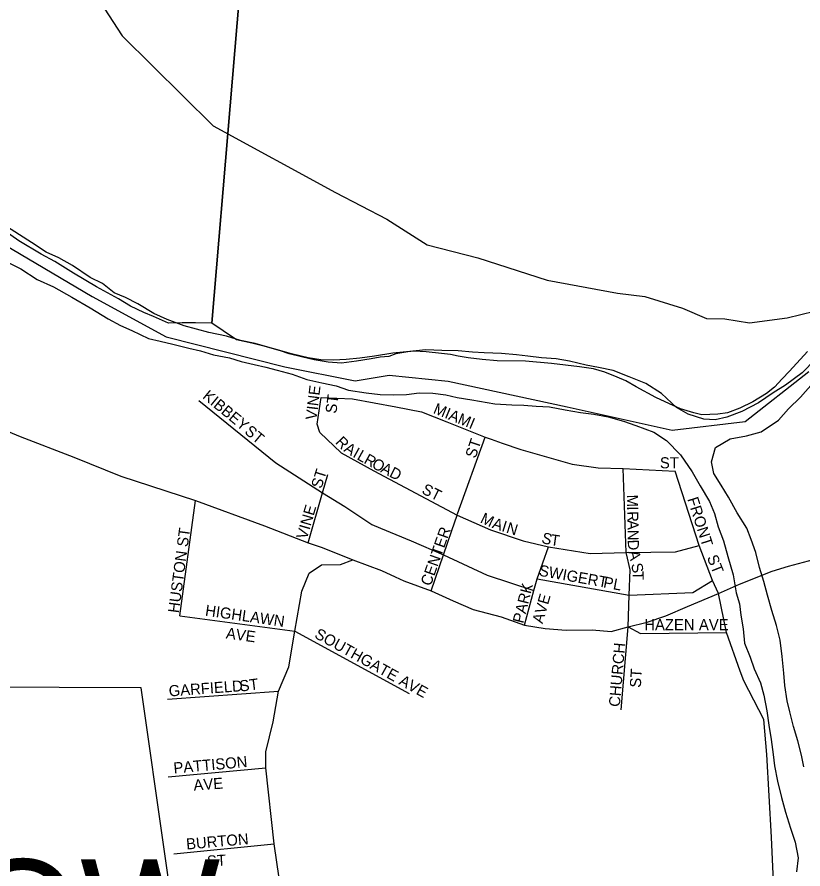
# Model space of a CAD drawing. Extents: x 1310247 to 1664935, y 284496 to 704931.
# Drawn here: x 1504369 to 1507915, y 496071 to 499915 of the extents above; entities that cross this region are included whole.
import ezdxf

# ---------------------------------------------------------------- set-up
doc = ezdxf.new("R2010")
doc.units = 0
for name, color, linetype in [('GM_P_State_Shield', 7, 'Continuous'), ('GM_X_City_Street', 7, 'Continuous'), ('GM_X_Corporation_Text', 7, 'Continuous'), ('GM_X_County', 7, 'Continuous'), ('GM_X_County_Road_Text', 7, 'Continuous'), ('GM_X_County_Subdivision', 7, 'Continuous'), ('GM_X_Interchange_Ramps', 7, 'Continuous'), ('GM_X_Major_Lake_Text', 7, 'Continuous'), ('GM_X_Rail_Line', 7, 'Continuous')]:
    doc.layers.add(name, color=color, linetype=linetype)

msp = doc.modelspace()

# ---------------------------------------------------------------- linework, layer by layer
at = {"layer": 'GM_P_State_Shield'}
for points in [[(1504152.3, 498118.9), (1504383.2, 498021.7), (1504625.4, 497929.6), (1504837.2, 497843.3), (1505174.2, 497733.5), (1505486.3, 497618.6), (1505682.3, 497542.5), (1505745.9, 497521.2), (1505884.5, 497466.3), (1506013, 497417.7), (1506075.5, 497389.1)], [(1506075.5, 497389.1), (1506114.1, 497371.5), (1506237.8, 497326.1), (1506336.3, 497281.6), (1506427.4, 497241.7), (1506553.5, 497208), (1506658.5, 497171.4), (1506752, 497155.5), (1506846.8, 497148.1), (1506964.2, 497149.3), (1507049.1, 497143.1), (1507126.4, 497163), (1507212.6, 497184.2), (1507296.2, 497212.9), (1507393.6, 497255.4), (1507533.4, 497314.1), (1507628.2, 497356.5), (1507775.5, 497415.2), (1507849.1, 497437.6), (1507962.7, 497467.6), (1508131.3, 497493.8), (1508329.7, 497516.3)]]:
    msp.add_lwpolyline(points, dxfattribs=at)
at = {"layer": 'GM_X_City_Street'}
for points in [[(1507971.6, 498370.8), (1507911.8, 498310.1), (1507836.1, 498253.9), (1507781, 498219.2), (1507713.6, 498174.8), (1507638.3, 498134.5), (1507571.4, 498110.1), (1507518.9, 498097.4), (1507466.8, 498100.7), (1507397.1, 498122.5), (1507343.7, 498153.9), (1507277, 498215.7), (1507205.9, 498261.6), (1507130.4, 498291.6), (1507058.9, 498319.4), (1506993, 498333.1), (1506937.1, 498344.5), (1506861.2, 498362.5), (1506801.3, 498372), (1506735.2, 498377.6), (1506673.1, 498385.2), (1506623.1, 498390.5), (1506555, 498396.2), (1506476.8, 498400.1), (1506424.7, 498403.5), (1506358.6, 498409.1), (1506286.4, 498410.9), (1506214.1, 498412.7), (1506125.6, 498404.9), (1506065.2, 498398.4), (1505982.6, 498384.4), (1505916.1, 498376.1), (1505853.7, 498369.6), (1505797.4, 498367), (1505739.3, 498368.5), (1505683.3, 498377.9), (1505607.5, 498395.8), (1505527.7, 498417.9), (1505444.1, 498442), (1505378.2, 498455.7), (1505314.4, 498475.3), (1505234.6, 498491.4), (1505178.7, 498506.8), (1505122.9, 498522.2), (1505047.4, 498550.2), (1504985.9, 498577.8), (1504914.7, 498621.6), (1504859.2, 498649.1), (1504807.6, 498670.4), (1504754.5, 498711.9), (1504699, 498739.3), (1504620.1, 498793.4), (1504558.7, 498829), (1504501.2, 498854.5), (1504434.1, 498898.3), (1504380.7, 498931.7), (1504321.5, 498969.3)], [(1504335.3, 498804.5), (1504386.8, 498779.2), (1504459.9, 498731.3), (1504533.3, 498697.3), (1504616.4, 498651.2), (1504699.5, 498603), (1504780.5, 498552.8), (1504835.9, 498523.4), (1504887.5, 498500), (1504962.9, 498464.1), (1505014.8, 498452.8), (1505072.6, 498439.3), (1505144.4, 498421.5), (1505196.3, 498408.1), (1505256, 498390.6), (1505328, 498376.8), (1505379.8, 498361.4), (1505439.6, 498347.9), (1505491.5, 498334.6), (1505543.3, 498321.3), (1505611.1, 498303.5), (1505676.8, 498279.8), (1505744.6, 498264.1), (1505808.5, 498250.5), (1505864.2, 498231), (1505944.2, 498219), (1506008.2, 498211.4), (1506066.4, 498210), (1506126.7, 498212.5), (1506183.1, 498219), (1506245.2, 498217.5), (1506303.3, 498210), (1506355.2, 498198.7), (1506421.1, 498187), (1506525.1, 498170.4), (1506601.2, 498164.5), (1506655.4, 498163.1), (1506711.5, 498159.7), (1506771.6, 498156.2), (1506841.5, 498142.4), (1506911.5, 498130.7), (1506971.5, 498123.1), (1507035.4, 498111.5), (1507105.2, 498091.7), (1507160.9, 498072.3), (1507242.4, 498042.2), (1507299.7, 498004.7), (1507362.2, 497939), (1507414.5, 497863.5), (1507451, 497800.4), (1507493.3, 497729.2), (1507516, 497674.5), (1507532.5, 497614), (1507557, 497551.2), (1507575.2, 497480.6), (1507599.2, 497397.8), (1507613.1, 497317.3), (1507627.9, 497266.8), (1507634.6, 497216.5), (1507645.1, 497154.1), (1507651.4, 497089.8), (1507675.9, 497027), (1507694.6, 496974.4), (1507723.1, 496911.6), (1507737.7, 496855.1), (1507752, 496784.6), (1507760.3, 496720.2), (1507770.7, 496655.8), (1507781, 496587.4), (1507785.7, 496537.1), (1507800, 496466.6), (1507818.2, 496394), (1507836.5, 496327.4), (1507858.7, 496254.6), (1507879.2, 496192), (1507893.4, 496121.5), (1507885.8, 496057.5)], [(1507918.1, 496531.8), (1507907.4, 496584.2), (1507891, 496648.8), (1507872.6, 496713.4), (1507856.2, 496779.9), (1507843.5, 496830.4), (1507833.2, 496898.8), (1507828.6, 496955), (1507820.5, 497029.4), (1507812.4, 497103.8), (1507796, 497170.3), (1507773.7, 497237.1), (1507755.4, 497305.7), (1507738.9, 497368.2), (1507718.5, 497430.9), (1507702.2, 497499.5), (1507681.6, 497558.1), (1507660.8, 497608.8), (1507618.4, 497678), (1507578.1, 497749.1), (1507545.4, 497802.1), (1507512.6, 497855), (1507501.9, 497907.4), (1507519.7, 497973.1), (1507586.9, 498011.5), (1507659.5, 498025.8), (1507726.3, 498044.1), (1507803.9, 498096.3), (1507849.4, 498147.3), (1507902.9, 498200.1), (1507960.8, 498264.8)]]:
    msp.add_lwpolyline(points, dxfattribs=at)
at = {"layer": 'GM_X_Corporation_Text'}
for points in [[(1505735.9, 498040.5), (1505723.4, 498078), (1505740.9, 498199)], [(1505740.9, 498199), (1505883.2, 498192.8), (1506077.9, 498156.6), (1506194, 498134.1), (1506308.9, 498089.2), (1506481.1, 498019.3), (1506507.8, 498009.7)], [(1505189.2, 498184.1), (1505537.4, 497903.2), (1505747.2, 497768.4), (1505848.3, 497707.2), (1505969.3, 497624.9), (1506009.2, 497608.4)], [(1505735.9, 498040.5), (1505832, 497948.2), (1505979.3, 497867), (1506354.4, 497667.5)], [(1506356.6, 497673.7), (1506481.1, 498019.3)], [(1506507.8, 498009.7), (1506557.3, 497991.9), (1506642.1, 497963.1), (1506874.3, 497897), (1506991.6, 497880.8), (1507104, 497878.3), (1507338.7, 497865.8)], [(1505682.3, 497542.5), (1505747.2, 497768.4), (1505772.1, 497850.8)], [(1507118.2, 497492.2), (1507116.8, 497498.3), (1507104, 497878.3)], [(1507533.4, 497314.1), (1507505.9, 497372.7), (1507446, 497530), (1507338.7, 497865.8)], [(1505103.9, 497212.9), (1505174.2, 497733.5)], [(1506237.8, 497326.1), (1506293.1, 497488.7), (1506330.4, 497598.5), (1506354.4, 497667.5), (1506356.6, 497673.7)], [(1506354.4, 497667.5), (1506504.8, 497601.1), (1506652.1, 497551.2), (1506767, 497523.8), (1506955.4, 497495), (1507116.8, 497498.3), (1507339.9, 497501.3), (1507446, 497530)], [(1506009.2, 497608.4), (1506147.8, 497551.2), (1506293.1, 497488.7), (1506489.8, 497396.4), (1506701, 497328.1)], [(1506658.5, 497171.4), (1506701, 497328.1), (1506715.3, 497380.7), (1506767, 497523.8)], [(1505624.3, 495659.1), (1505608.1, 495685.1), (1505574.8, 495855.8), (1505552, 496030), (1505529.1, 496185.1), (1505492.1, 496527), (1505491.8, 496600.2), (1505524.1, 496735.3), (1505549.3, 496873.5), (1505594.8, 496982.8), (1505622.6, 497144.1), (1505653.7, 497324.6), (1505687.2, 497405.2), (1505742.2, 497443.9), (1505828.3, 497445.1), (1505884.5, 497466.3)], [(1507126.4, 497163), (1507131.4, 497306.6), (1507135.2, 497420.2), (1507118.2, 497492.2)], [(1506715.3, 497380.7), (1507131.4, 497306.6), (1507417.3, 497319.1), (1507505.9, 497372.7)], [(1507631.8, 496964.1), (1507570.2, 497138), (1507533.4, 497314.1)], [(1505103.9, 497212.9), (1505622.6, 497144.1)], [(1507094.6, 496789.4), (1507126.4, 497163)], [(1507126.4, 497163), (1507181.4, 497133.1), (1507570.2, 497138)], [(1505622.6, 497144.1), (1506139, 496863)], [(1505048.6, 496836.9), (1505549.3, 496873.5)], [(1505051.2, 496486.5), (1505492.1, 496527)], [(1505076, 496138.7), (1505529.1, 496185.1)]]:
    msp.add_lwpolyline(points, dxfattribs=at)
at = {"layer": 'GM_X_County'}
for points in [[(1505662.2, 503437.3), (1505248.3, 498534.2), (1505174.4, 498535.5), (1505114.4, 498534.7), (1505052.4, 498533.8), (1504984.9, 498563.1), (1504941.3, 498581.9), (1504881.9, 498611), (1504826.5, 498644), (1504727.5, 498697.9), (1504624.7, 498759.8), (1504539.7, 498811.4), (1504478.3, 498844.5), (1504377.5, 498904.4), (1504288.7, 498966.1)], [(1507935.2, 498405.8), (1507853.6, 498317.3), (1507820.9, 498282), (1507786.2, 498244.6), (1507750.3, 498216.3), (1507689, 498178.5), (1507630.5, 498149.6), (1507574.1, 498128.6), (1507530.1, 498123.5), (1507458, 498120.8), (1507422.2, 498129.5), (1507362.5, 498146.6), (1507313, 498169.5), (1507251.5, 498198.6), (1507162.4, 498246.3), (1507115, 498273.2), (1507077.3, 498289.9), (1507021.7, 498312.9), (1506970, 498327.9), (1506906.2, 498337.1), (1506780.5, 498351.5), (1506662.8, 498361.7), (1506534.8, 498364.1), (1506466.9, 498369.3), (1506405.1, 498376.5), (1506359.3, 498385.3), (1506325.4, 498392), (1506283.5, 498396.8), (1506215.6, 498404), (1506159.7, 498407.1), (1506131.7, 498403.6), (1506077.5, 498394.6), (1506047.3, 498383.2), (1506007.3, 498379.9), (1505967.1, 498372.7), (1505900.9, 498361.9), (1505832.8, 498353.2), (1505772.9, 498358.3), (1505709.1, 498367.6), (1505659.3, 498380.5), (1505597.6, 498395.6), (1505557.9, 498408.4), (1505488.3, 498427.7), (1505428.5, 498442.8), (1505358.9, 498458.1), (1505299.7, 498499.2), (1505248.3, 498534.2), (1505662.2, 503437.3)]]:
    msp.add_lwpolyline(points, dxfattribs=at)
at = {"layer": 'GM_X_County_Road_Text'}
msp.add_lwpolyline([(1504762.6, 499954.6), (1504844.4, 499830.8), (1505253.7, 499424.5), (1505805.4, 499123.7), (1506037.7, 499003.2), (1506220, 498887.6), (1506447.4, 498828), (1506760.3, 498727), (1507078.3, 498669), (1507201.9, 498653.8), (1507371, 498600.8), (1507479.5, 498555.4), (1507562.8, 498552.9), (1507673.9, 498535.2), (1507842.9, 498558), (1507966.6, 498588.2), (1508208.8, 498777.5), (1508244.7, 498830.4)], dxfattribs=at)
at = {"layer": 'GM_X_County_Subdivision'}
msp.add_lwpolyline([(1507640.9, 495264.3), (1507686, 495328.7), (1507768.8, 495456.3), (1507801, 495569.4), (1507785.1, 495948.5), (1507773.5, 496214), (1507752.3, 496587.5), (1507737.5, 496746.1), (1507647.6, 496919.6), (1507631.8, 496964.1)], dxfattribs=at)
at = {"layer": 'GM_X_Major_Lake_Text'}
for points in [[(1504165.2, 498973.6), (1504708.1, 498654.6), (1505042.3, 498472.3), (1505577.5, 498335.9), (1505895.2, 498274.1), (1506047.7, 498298.4), (1506313.8, 498271.3), (1506851.3, 498156.9), (1507324.7, 498051.2), (1507653.7, 498089.6), (1507941, 498314.9)], [(1505142.2, 495390.9), (1504929.1, 496888.4), (1503819.6, 496892.3)]]:
    msp.add_lwpolyline(points, dxfattribs=at)

# ---------------------------------------------------------------- texts
at = {"layer": 'GM_X_Interchange_Ramps'}
msp.add_text('MORROW', height=500, rotation=0, dxfattribs=at).set_placement((1502091.8, 495614.1))
at = {"layer": 'GM_X_Rail_Line'}
for s, rotation, p in [('KIBBEY', 320.4772, (1505202.9, 498197.8)), ('VINE', 83.0927, (1505720.1, 498094.9)), ('ST', 82.8783, (1505809.8, 498123.9)), ('MIAMI', 337.4817, (1506243.4, 498128.9)), ('ST', 320.2016, (1505392.2, 498039.4)), ('R', 313.643, (1505802.7, 497994.1)), ('ST', 71.5607, (1506437.6, 497920.7)), ('A', 327.3031, (1505840.1, 497957.2)), ('I', 331.0012, (1505880.1, 497931.6)), ('L', 330.8313, (1505899.3, 497921)), ('R', 330.8275, (1505930.1, 497903.8)), ('O', 332.1155, (1505965.7, 497883.9)), ('ST', 0, (1507269.4, 497878.8)), ('A', 333.4048, (1506005.7, 497862.8)), ('D', 333.4347, (1506045.1, 497843.1)), ('ST', 72.6452, (1505742.4, 497784.2)), ('ST', 333.435, (1506191.2, 497767.8)), ('M', 271.0383, (1507120.4, 497759.5)), ('FRONT', 287.6491, (1507392.7, 497740.2)), ('VINE', 73.8118, (1505676.3, 497555.2)), ('I', 271.0593, (1507121.3, 497706.7)), ('M', 334.5022, (1506455.4, 497635.7)), ('A', 341.2367, (1506509, 497610.5)), ('R', 271.0443, (1507121.7, 497684.7)), ('HUSTON ST', 82.4038, (1505099.6, 497223.8)), ('CENTER', 70.5579, (1506235.3, 497344.5)), ('I', 342.9263, (1506552.2, 497595.9)), ('N', 342.8989, (1506573.2, 497589.4)), ('A', 271.0521, (1507122.5, 497645.1)), ('S', 343.8032, (1506731.6, 497543.7)), ('T', 351.9734, (1506773, 497532.3)), ('N', 271.0273, (1507123.3, 497601.1)), ('D', 271.9314, (1507124.1, 497556.3)), ('A', 282.4777, (1507126.8, 497502.4)), ('ST', 291.8039, (1507480.5, 497476.9)), ('SWIGERT', 349.78, (1506721, 497394.6)), ('S', 281.0259, (1507139.2, 497446.7)), ('PL', 349.3721, (1507011.5, 497341.8)), ('T', 271.7763, (1507145.7, 497414.3)), ('PARK', 75.9666, (1506653, 497176.5)), ('AVE', 74.0556, (1506740.2, 497175.1)), ('HIGHLAWN', 351.766, (1505215.9, 497214.3)), ('HAZEN', 0, (1507199, 497148.4)), ('AVE', 0, (1507445.4, 497148.4)), ('AVE', 352.1434, (1505309.7, 497111.5)), ('SOUTHGATE AVE', 330.9932, (1505707.5, 497116.4)), ('CHURCH', 85.0717, (1507088.4, 496801)), ('ST', 86.4254, (1507183, 496887.8)), ('GARFIELD', 4.1455, (1505055.5, 496849.2)), ('ST', 7.1217, (1505376.2, 496871.1)), ('PATTISON', 5.1177, (1505077.3, 496501.5)), ('AVE', 3.9506, (1505167, 496424.5)), ('BURTON', 5.0142, (1505134.5, 496158.4)), ('ST', 3.5746, (1505228.1, 496081.3))]:
    msp.add_text(s, height=50, rotation=rotation, dxfattribs=at).set_placement(p)

doc.saveas('drawing.dxf')
